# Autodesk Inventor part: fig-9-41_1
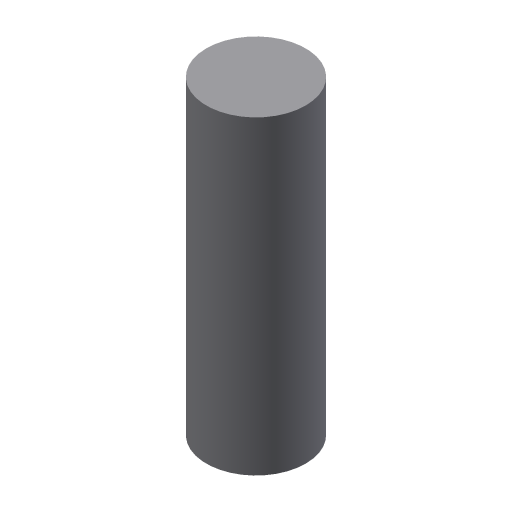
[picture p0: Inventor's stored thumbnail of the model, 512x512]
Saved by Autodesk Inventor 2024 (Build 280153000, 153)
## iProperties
Created: 2013-03
Part Number: fig-9-41_1
Material: Generic
Document SubType Name: Modeling
Designer: CADCIM
Density: 1 g/cm^3
Appearance: Default
Author: CADCIM
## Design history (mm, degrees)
sketch "Sketch1"
  geometry: C1 r 4 at (0, 0); 1 further point
  constraints: 1 centre point, 1 coincident
  dimensions: "d0" = 8 diameter of C1
extrude "Extrusion1" new body sketch "Sketch1" stored distance "d2" = 25; taper "d3" = 0 deg
body "Solid1"
